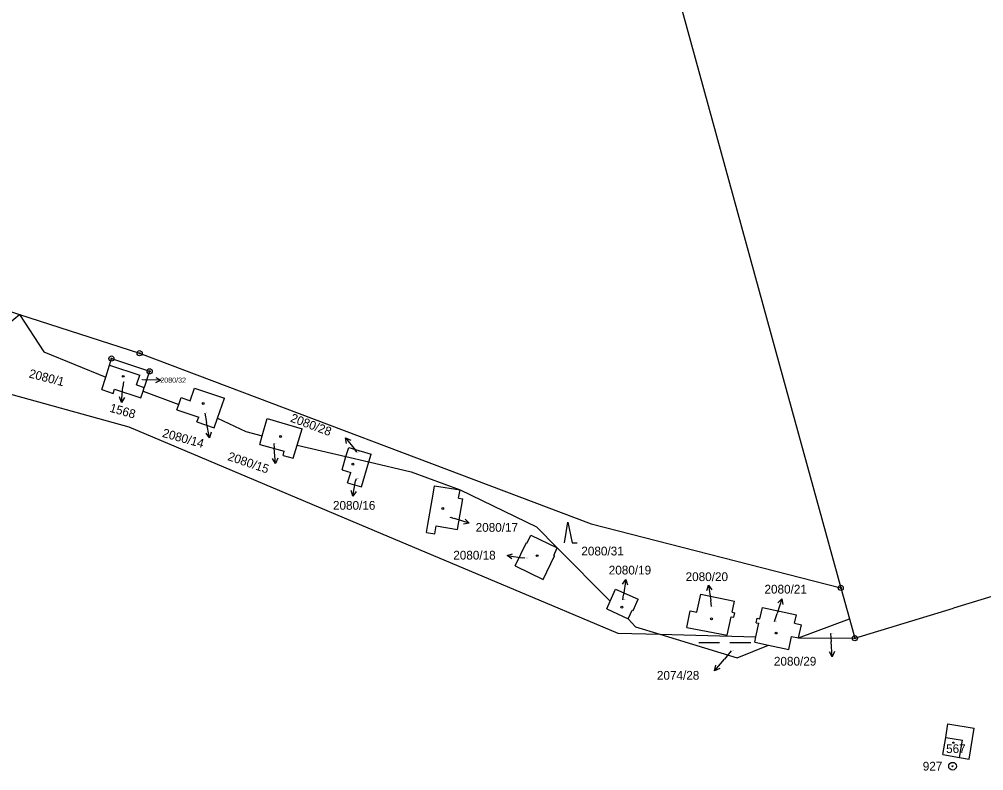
# Model space of a CAD drawing. Extents: x -763205 to -760228, y -1155311 to -1152844.
# Drawn here: x -762716.8 to -762529.9, y -1153578.5 to -1153432.8 of the extents above; entities that cross this region are included whole.
import ezdxf

# ---------------------------------------------------------------- set-up
doc = ezdxf.new("R2010")
doc.units = 0
for name, color, linetype in [('Vrstva 1', 7, 'Continuous'), ('Vrstva 13', 7, 'Continuous'), ('Vrstva 16', 7, 'Continuous'), ('Vrstva 17', 7, 'Continuous'), ('Vrstva 18', 7, 'Continuous'), ('Vrstva 19', 7, 'Continuous'), ('Vrstva 24', 7, 'Continuous'), ('Vrstva 25', 7, 'Continuous'), ('Vrstva 4', 7, 'Continuous'), ('Vrstva 6', 7, 'Continuous'), ('Vrstva 62', 7, 'Continuous')]:
    doc.layers.add(name, color=color, linetype=linetype)

msp = doc.modelspace()

# ---------------------------------------------------------------- linework, layer by layer
at = {"layer": 'Vrstva 1'}
for p, q in [((-762791.7, -1153465.84), (-762716.71, -1153490.04)), ((-762776.64, -1153489.33), (-762695.53, -1153511.84)), ((-762716.71, -1153490.04), (-762693.44, -1153497.55)), ((-762693.44, -1153497.55), (-762605.92, -1153530.65)), ((-762700.02, -1153502.17), (-762699.3, -1153499.84)), ((-762699.3, -1153499.84), (-762698.91, -1153498.59)), ((-762699.3, -1153499.84), (-762693.41, -1153501.78)), ((-762698.91, -1153498.59), (-762691.5, -1153501.06)), ((-762694.05, -1153503.71), (-762693.41, -1153501.78)), ((-762691.5, -1153501.06), (-762692.53, -1153504.21)), ((-762700.77, -1153504.58), (-762700.02, -1153502.17)), ((-762694.05, -1153503.71), (-762692.53, -1153504.21)), ((-762700.77, -1153504.58), (-762698.59, -1153505.34)), ((-762698.59, -1153505.34), (-762698.31, -1153504.5)), ((-762698.31, -1153504.5), (-762693.19, -1153506.22)), ((-762693.19, -1153506.22), (-762692.76, -1153504.92)), ((-762692.76, -1153504.92), (-762692.53, -1153504.21)), ((-762683.66, -1153506.77), (-762682.81, -1153504.33)), ((-762682.81, -1153504.33), (-762677.02, -1153506.28)), ((-762686.21, -1153508.54), (-762685.84, -1153507.48)), ((-762685.84, -1153507.48), (-762685.39, -1153506.17)), ((-762685.39, -1153506.17), (-762683.66, -1153506.77)), ((-762678.34, -1153510.15), (-762677.02, -1153506.28)), ((-762686.21, -1153508.54), (-762684.48, -1153509.14)), ((-762684.48, -1153509.14), (-762681.94, -1153509.97)), ((-762682.33, -1153510.88), (-762681.94, -1153509.97)), ((-762682.33, -1153510.88), (-762678.97, -1153512.02)), ((-762678.97, -1153512.02), (-762678.34, -1153510.15)), ((-762669.69, -1153513.58), (-762668.7, -1153510.22)), ((-762668.7, -1153510.22), (-762661.95, -1153512.23)), ((-762695.53, -1153511.84), (-762646.29, -1153532.61)), ((-762662.91, -1153515.39), (-762661.95, -1153512.23)), ((-762670.17, -1153515.23), (-762669.69, -1153513.58)), ((-762670.17, -1153515.23), (-762665.41, -1153516.55)), ((-762665.64, -1153517.38), (-762665.41, -1153516.55)), ((-762663.68, -1153517.93), (-762662.91, -1153515.39)), ((-762653.45, -1153517.59), (-762652.91, -1153515.8)), ((-762652.91, -1153515.8), (-762648.55, -1153517.1)), ((-762665.64, -1153517.38), (-762663.68, -1153517.93)), ((-762654.22, -1153520.14), (-762653.45, -1153517.59)), ((-762650.46, -1153523.47), (-762649.01, -1153518.62)), ((-762649.01, -1153518.62), (-762648.55, -1153517.1)), ((-762654.22, -1153520.14), (-762652.51, -1153520.67)), ((-762653.13, -1153522.65), (-762652.51, -1153520.67)), ((-762653.13, -1153522.65), (-762650.46, -1153523.47)), ((-762636.58, -1153524.89), (-762636.31, -1153523.27)), ((-762636.31, -1153523.27), (-762631.35, -1153524.07)), ((-762631.62, -1153525.68), (-762631.35, -1153524.07)), ((-762637.58, -1153530.77), (-762636.58, -1153524.89)), ((-762631.82, -1153531.74), (-762630.81, -1153525.81)), ((-762631.62, -1153525.68), (-762630.81, -1153525.81)), ((-762637.84, -1153532.3), (-762637.58, -1153530.77)), ((-762636.23, -1153532.57), (-762635.97, -1153531.04)), ((-762635.97, -1153531.04), (-762631.82, -1153531.74)), ((-762605.92, -1153530.65), (-762557.58, -1153543.04)), ((-762646.29, -1153532.61), (-762614.87, -1153545.86)), ((-762637.84, -1153532.3), (-762636.23, -1153532.57)), ((-762618.35, -1153534.3), (-762617.65, -1153532.85)), ((-762617.65, -1153532.85), (-762612.5, -1153535.31)), ((-762620.65, -1153538.8), (-762618.48, -1153534.24)), ((-762618.48, -1153534.24), (-762618.35, -1153534.3)), ((-762613.18, -1153536.76), (-762612.5, -1153535.31)), ((-762615.25, -1153541.4), (-762613.05, -1153536.82)), ((-762613.18, -1153536.76), (-762613.05, -1153536.82)), ((-762620.65, -1153538.8), (-762615.25, -1153541.4)), ((-762602.26, -1153545.62), (-762601.22, -1153543.28)), ((-762601.22, -1153543.28), (-762596.83, -1153545.23)), ((-762585.44, -1153547.78), (-762584.69, -1153544.25)), ((-762584.69, -1153544.25), (-762578.17, -1153545.63)), ((-762614.87, -1153545.86), (-762600.79, -1153551.8)), ((-762602.92, -1153547.1), (-762602.26, -1153545.62)), ((-762597.81, -1153547.44), (-762596.83, -1153545.23)), ((-762578.62, -1153547.74), (-762578.17, -1153545.63)), ((-762602.92, -1153547.1), (-762598.74, -1153549.03)), ((-762598.74, -1153549.03), (-762598, -1153547.36)), ((-762598, -1153547.36), (-762597.81, -1153547.44)), ((-762587.39, -1153550.75), (-762586.78, -1153547.5)), ((-762586.78, -1153547.5), (-762585.44, -1153547.78)), ((-762578.62, -1153547.74), (-762578.08, -1153547.86)), ((-762578.27, -1153548.75), (-762578.08, -1153547.86)), ((-762573.23, -1153549.03), (-762572.76, -1153546.83)), ((-762572.76, -1153546.83), (-762566.17, -1153548.28)), ((-762566.53, -1153549.9), (-762566.17, -1153548.28)), ((-762579.58, -1153552.22), (-762578.82, -1153548.63)), ((-762578.82, -1153548.63), (-762578.27, -1153548.75)), ((-762574, -1153552.53), (-762573.43, -1153549.92)), ((-762573.98, -1153549.8), (-762573.78, -1153548.91)), ((-762573.98, -1153549.8), (-762573.43, -1153549.92)), ((-762573.78, -1153548.91), (-762573.23, -1153549.03)), ((-762566.53, -1153549.9), (-762565.17, -1153550.19)), ((-762565.75, -1153552.76), (-762565.17, -1153550.19)), ((-762600.79, -1153551.8), (-762592.66, -1153552.02)), ((-762592.66, -1153552.02), (-762574, -1153552.53)), ((-762587.39, -1153550.75), (-762579.58, -1153552.22)), ((-762574.23, -1153553.56), (-762574, -1153552.53)), ((-762574.23, -1153553.56), (-762571.58, -1153554.14)), ((-762571.58, -1153554.14), (-762567.65, -1153555.01)), ((-762567.65, -1153555.01), (-762567.09, -1153552.46)), ((-762567.09, -1153552.46), (-762565.75, -1153552.76)), ((-762565.75, -1153552.76), (-762554.85, -1153552.8)), ((-762537.81, -1153575.38), (-762537.24, -1153572.03)), ((-762537.24, -1153572.03), (-762533.99, -1153572.57)), ((-762534.55, -1153575.92), (-762533.99, -1153572.57)), ((-762537.81, -1153575.38), (-762534.55, -1153575.92))]:
    msp.add_line(p, q, dxfattribs=at)
at = {"layer": 'Vrstva 13'}
for p, q in [((-762629.54, -1153281.15), (-762569.44, -1153499.86)), ((-762569.44, -1153499.86), (-762557.58, -1153543.04)), ((-762557.58, -1153543.04), (-762555.91, -1153549.02)), ((-762527.43, -1153544.47), (-762535.71, -1153546.98)), ((-762554.85, -1153552.8), (-762535.71, -1153546.98)), ((-762555.91, -1153549.02), (-762554.85, -1153552.8))]:
    msp.add_line(p, q, dxfattribs=at)
at = {"layer": 'Vrstva 16'}
for p, q in [((-762696.58, -1153503.08), (-762696.67, -1153504.09)), ((-762692.89, -1153502.68), (-762692.32, -1153502.7)), ((-762689.322, -1153502.8), (-762692.32, -1153502.7)), ((-762696.947, -1153507.077), (-762696.67, -1153504.09)), ((-762680.82, -1153509.15), (-762680.46, -1153510.99)), ((-762679.875, -1153513.932), (-762680.46, -1153510.99)), ((-762653.546, -1153513.933), (-762651.69, -1153516.29)), ((-762667.43, -1153515.05), (-762667.35, -1153515.95)), ((-762667.082, -1153518.938), (-762667.35, -1153515.95)), ((-762651.32, -1153516.76), (-762651.69, -1153516.29)), ((-762652.135, -1153525.27), (-762651.59, -1153522.32)), ((-762651.51, -1153521.91), (-762651.59, -1153522.32)), ((-762633.34, -1153529.35), (-762632.44, -1153529.62)), ((-762629.564, -1153530.473), (-762632.44, -1153529.62)), ((-762622.247, -1153536.795), (-762619.28, -1153537.24)), ((-762618.79, -1153537.31), (-762619.28, -1153537.24)), ((-762599.231, -1153541.404), (-762599.68, -1153544.37)), ((-762583.206, -1153542.502), (-762582.77, -1153545.47)), ((-762599.83, -1153545.37), (-762599.68, -1153544.37)), ((-762582.6, -1153546.65), (-762582.77, -1153545.47)), ((-762568.966, -1153545.182), (-762569.91, -1153548.03)), ((-762570.43, -1153549.59), (-762569.91, -1153548.03)), ((-762559.53, -1153551.92), (-762559.42, -1153553.43)), ((-762559.206, -1153556.422), (-762559.42, -1153553.43)), ((-762578.81, -1153555.27), (-762580.11, -1153556.84)), ((-762582.026, -1153559.149), (-762580.11, -1153556.84))]:
    msp.add_line(p, q, dxfattribs=at)
for points in [[(-762690.304, -1153502.267), (-762689.322, -1153502.8), (-762690.338, -1153503.266)], [(-762696.357, -1153506.128), (-762696.947, -1153507.077), (-762697.353, -1153506.035)], [(-762679.579, -1153512.854), (-762679.875, -1153513.932), (-762680.56, -1153513.049)], [(-762653.32, -1153515.028), (-762653.546, -1153513.933), (-762652.534, -1153514.409)], [(-762666.673, -1153517.897), (-762667.082, -1153518.938), (-762667.669, -1153517.987)], [(-762651.461, -1153524.378), (-762652.135, -1153525.27), (-762652.445, -1153524.196)], [(-762630.38, -1153529.709), (-762629.564, -1153530.473), (-762630.665, -1153530.668)], [(-762621.332, -1153537.438), (-762622.247, -1153536.795), (-762621.184, -1153536.449)], [(-762599.875, -1153542.318), (-762599.231, -1153541.404), (-762598.886, -1153542.467)], [(-762583.556, -1153543.564), (-762583.206, -1153542.502), (-762582.566, -1153543.419)], [(-762569.755, -1153545.974), (-762568.966, -1153545.182), (-762568.806, -1153546.289)], [(-762558.779, -1153555.389), (-762559.206, -1153556.422), (-762559.776, -1153555.461)], [(-762581.002, -1153558.698), (-762582.026, -1153559.149), (-762581.772, -1153558.06)]]:
    msp.add_lwpolyline(points, dxfattribs=at)
at = {"layer": 'Vrstva 24'}
for centre, radius in [((-762698.91, -1153498.59), 0.5), ((-762693.44, -1153497.55), 0.5), ((-762693.44, -1153497.55), 0.1), ((-762698.91, -1153498.59), 0.1), ((-762691.5, -1153501.06), 0.5), ((-762691.5, -1153501.06), 0.1), ((-762557.58, -1153543.04), 0.5), ((-762557.58, -1153543.04), 0.1), ((-762554.85, -1153552.8), 0.5), ((-762554.85, -1153552.8), 0.1), ((-762535.91, -1153577.62), 0.75), ((-762535.91, -1153577.62), 0.1)]:
    msp.add_circle(centre, radius, dxfattribs=at)
at = {"layer": 'Vrstva 25'}
for p, q in [((-762585.075, -1153553.62), (-762581.055, -1153553.62)), ((-762579.045, -1153553.62), (-762575.025, -1153553.62))]:
    msp.add_line(p, q, dxfattribs=at)
msp.add_lwpolyline([(-762611.13, -1153534.32), (-762610.43, -1153530.32), (-762609.63, -1153534.32), (-762608.63, -1153534.32)], dxfattribs=at)
for centre, radius in [((-762696.61, -1153502.03), 0.175), ((-762681.11, -1153507.3), 0.175), ((-762666.12, -1153513.71), 0.175), ((-762652.1, -1153519.05), 0.175), ((-762634.71, -1153527.66), 0.175), ((-762616.4, -1153536.8), 0.175), ((-762600, -1153546.79), 0.175), ((-762582.61, -1153549.06), 0.175), ((-762570.11, -1153551.8), 0.175), ((-762535.74, -1153573.06), 0.117)]:
    msp.add_circle(centre, radius, dxfattribs=at)
at = {"layer": 'Vrstva 4'}
for p, q in [((-762537.24, -1153572.03), (-762536.8, -1153569.38)), ((-762536.8, -1153569.38), (-762531.69, -1153570.22)), ((-762532.68, -1153576.24), (-762531.69, -1153570.22)), ((-762534.55, -1153575.92), (-762532.68, -1153576.24))]:
    msp.add_line(p, q, dxfattribs=at)
at = {"layer": 'Vrstva 6'}
for p, q in [((-762720.03, -1153492.79), (-762716.71, -1153490.04)), ((-762716.71, -1153490.04), (-762712.03, -1153497.27)), ((-762712.03, -1153497.27), (-762700.02, -1153502.17)), ((-762692.76, -1153504.92), (-762685.84, -1153507.48)), ((-762678.34, -1153510.15), (-762672.83, -1153512.74)), ((-762672.83, -1153512.74), (-762669.69, -1153513.58)), ((-762662.91, -1153515.39), (-762653.45, -1153517.59)), ((-762653.45, -1153517.59), (-762649.01, -1153518.62)), ((-762649.01, -1153518.62), (-762640.82, -1153520.53)), ((-762640.82, -1153520.53), (-762631.35, -1153524.07)), ((-762631.35, -1153524.07), (-762616.53, -1153531.24)), ((-762616.53, -1153531.24), (-762612.5, -1153535.31)), ((-762612.5, -1153535.31), (-762602.26, -1153545.62)), ((-762598.74, -1153549.03), (-762597.35, -1153550.59)), ((-762565.75, -1153552.76), (-762555.91, -1153549.02)), ((-762597.35, -1153550.59), (-762592.66, -1153552.02)), ((-762592.66, -1153552.02), (-762577.63, -1153556.61)), ((-762577.63, -1153556.61), (-762571.58, -1153554.14))]:
    msp.add_line(p, q, dxfattribs=at)

# ---------------------------------------------------------------- texts
at = {"layer": 'Vrstva 16'}
for s, rotation, p in [('1568', 344.29034, (-762699.374, -1153508.88)), ('2080/28', 339.59209, (-762664.357, -1153510.779)), ('2080/14', 344.51952, (-762689.173, -1153513.75)), ('2080/15', 341.08178, (-762676.501, -1153518.236))]:
    msp.add_text(s, height=1.7, rotation=rotation, dxfattribs=at).set_placement(p)
for s, p in [('2080/16', (-762655.973, -1153527.9)), ('2080/17', (-762628.323, -1153532.17)), ('2080/18', (-762632.664, -1153537.56)), ('2080/19', (-762602.533, -1153540.45)), ('2080/20', (-762587.633, -1153541.73)), ('2080/21', (-762572.353, -1153544.15)), ('2080/29', (-762570.527, -1153558.12)), ('2074/28', (-762593.199, -1153560.85))]:
    msp.add_text(s, height=1.7, dxfattribs=at).set_placement(p)
at = {"layer": 'Vrstva 17'}
msp.add_text('927', height=1.7, dxfattribs=at).set_placement((-762541.677, -1153578.47))
at = {"layer": 'Vrstva 18'}
msp.add_text('2080/1', height=1.7, rotation=345.43626, dxfattribs=at).set_placement((-762715.02, -1153502.23))
for s, height, p in [('2080/32', 0.1, (-762693.192, -1153502.68)), ('2080/14', 0.1, (-762680.806, -1153509.15)), ('2080/15', 0.1, (-762667.416, -1153515.05)), ('2080/28', 0.1, (-762651.306, -1153516.76)), ('2080/16', 0.1, (-762651.496, -1153521.91)), ('2080/17', 0.1, (-762633.326, -1153529.35)), ('2080/31', 1.7, (-762607.843, -1153536.76)), ('2080/18', 0.1, (-762618.776, -1153537.31)), ('2080/19', 0.1, (-762599.816, -1153545.37)), ('2080/20', 0.1, (-762582.586, -1153546.65)), ('2080/21', 0.1, (-762570.416, -1153549.59)), ('2080/29', 0.1, (-762559.516, -1153551.92)), ('2074/28', 0.1, (-762578.796, -1153555.27))]:
    msp.add_text(s, height=height, dxfattribs=at).set_placement(p)
at = {"layer": 'Vrstva 19'}
for s, height, p in [('1568', 0.1, (-762696.719, -1153503.08)), ('567', 1.7, (-762537.161, -1153575.07))]:
    msp.add_text(s, height=height, dxfattribs=at).set_placement(p)
at = {"layer": 'Vrstva 62'}
msp.add_text('2080/32', height=1, dxfattribs=at).set_placement((-762689.443, -1153503.28))

doc.saveas('drawing.dxf')
